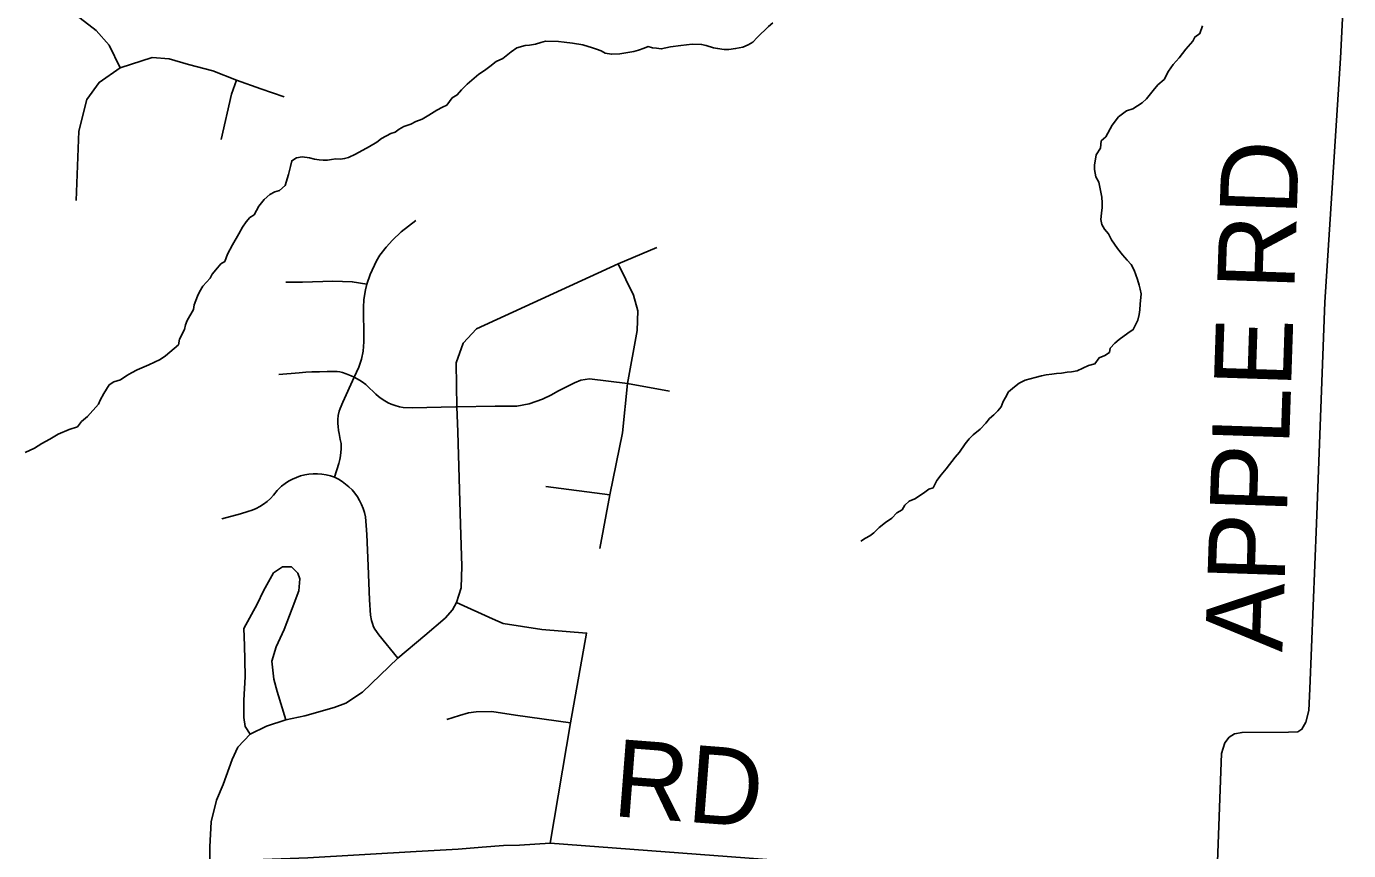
# Model space of a CAD drawing. Extents: x 0 to 34, y 0 to 22.
# Drawn here: x 3.128 to 4.1, y 15.409 to 16.016 of the extents above; entities that cross this region are included whole.
import ezdxf

# ---------------------------------------------------------------- set-up
doc = ezdxf.new("R2010")
doc.units = 0
for name, color, linetype in [('GM_X_Minor_River', 7, 'Continuous'), ('GM_X_Township_Road', 7, 'Continuous'), ('GM_X_Township_Road_Text', 7, 'Continuous')]:
    doc.layers.add(name, color=color, linetype=linetype)

msp = doc.modelspace()

# ---------------------------------------------------------------- linework, layer by layer
at = {"layer": 'GM_X_Minor_River'}
for points in [[(3.67652, 16.01808), (3.67344, 16.01547), (3.66494, 16.00726), (3.66184, 16.00389), (3.65839, 16.00205), (3.65455, 16.00022), (3.64921, 15.99917), (3.64426, 15.9985), (3.64084, 15.99856), (3.63591, 15.9994), (3.63288, 15.99984)], [(3.99241, 16.01596), (3.99042, 16.01029), (3.98695, 16.00769), (3.98538, 16.00467), (3.98034, 15.99868), (3.97529, 15.99231), (3.97103, 15.98744), (3.96752, 15.98256), (3.96438, 15.97653), (3.95975, 15.97243), (3.95626, 15.96831), (3.95122, 15.96232), (3.94812, 15.95933), (3.94121, 15.9549), (3.93662, 15.95345), (3.93084, 15.94899), (3.92618, 15.94299), (3.92148, 15.93433), (3.918, 15.93135), (3.91753, 15.92604), (3.91441, 15.92115), (3.91314, 15.91357), (3.91309, 15.91015), (3.91414, 15.90481), (3.91635, 15.90097), (3.91775, 15.89372), (3.91845, 15.88991), (3.91876, 15.88572), (3.9187, 15.88231), (3.91825, 15.87813), (3.9178, 15.87358), (3.91849, 15.86976), (3.92033, 15.86631), (3.92332, 15.86284), (3.92553, 15.85862), (3.92998, 15.85207), (3.9337, 15.84745), (3.93706, 15.84359), (3.94005, 15.8405), (3.94226, 15.83628), (3.94481, 15.82939), (3.94588, 15.82519), (3.94658, 15.82214), (3.94729, 15.8187)], [(3.63288, 15.99984), (3.62758, 16.00145), (3.62418, 16.00227), (3.61733, 16.00239), (3.60895, 16.0014), (3.60133, 16.00039), (3.59447, 15.99899), (3.59105, 15.99943), (3.58802, 15.99986), (3.58499, 16.00068), (3.58193, 15.99959), (3.57772, 15.99815), (3.57429, 15.99706), (3.56399, 15.99535), (3.5579, 15.99507), (3.55336, 15.99591), (3.55034, 15.99748), (3.54694, 15.99868), (3.54392, 15.99988), (3.53673, 16.0019), (3.52915, 16.00318), (3.52308, 16.00404), (3.5189, 16.0045), (3.5094, 16.00466), (3.50596, 16.00359), (3.50214, 16.00251), (3.49757, 16.00183), (3.49452, 16.0015), (3.48841, 15.99971), (3.48418, 15.99675), (3.47801, 15.99191), (3.47303, 15.98972), (3.46841, 15.986), (3.46456, 15.98303), (3.46033, 15.98044), (3.45532, 15.97597), (3.45184, 15.97299), (3.44759, 15.96888), (3.44449, 15.96513), (3.44065, 15.96292), (3.43676, 15.95767), (3.43369, 15.9562), (3.42948, 15.95399), (3.42371, 15.95029), (3.41872, 15.94734), (3.41413, 15.94552), (3.41029, 15.94369), (3.40532, 15.94188), (3.40187, 15.94004), (3.39879, 15.93781), (3.39573, 15.93672), (3.38883, 15.93304), (3.38536, 15.93044), (3.37998, 15.92712), (3.36962, 15.9216), (3.36464, 15.91902), (3.36159, 15.91832), (3.35854, 15.91799), (3.35512, 15.91805), (3.35207, 15.91772), (3.34902, 15.91702), (3.34598, 15.91707), (3.34294, 15.9175), (3.33953, 15.91794), (3.33574, 15.91877), (3.33044, 15.91962), (3.32624, 15.91894), (3.32278, 15.91672), (3.32195, 15.91255), (3.32033, 15.9065), (3.31792, 15.89856), (3.31367, 15.89483), (3.31023, 15.89375), (3.30678, 15.89191), (3.30253, 15.88819), (3.29865, 15.88331), (3.29512, 15.87691), (3.29205, 15.87507), (3.28933, 15.87169), (3.28661, 15.86794), (3.28387, 15.86305), (3.27916, 15.85477), (3.27563, 15.84799), (3.27364, 15.8427), (3.27057, 15.84086), (3.26823, 15.83786), (3.26436, 15.83336), (3.26279, 15.83035), (3.25737, 15.82436), (3.25501, 15.82022), (3.25344, 15.81721), (3.25224, 15.81381), (3.25105, 15.81079), (3.25062, 15.80738), (3.24592, 15.7991), (3.24473, 15.79608), (3.24391, 15.79267), (3.24037, 15.78551), (3.23954, 15.78135), (3.2299, 15.77315), (3.22605, 15.77056)], [(3.94729, 15.8187), (3.94678, 15.81111), (3.94633, 15.80693), (3.94589, 15.80352), (3.94506, 15.79935), (3.94153, 15.79257), (3.93768, 15.78998), (3.93114, 15.78515), (3.92805, 15.78254), (3.92457, 15.77881), (3.92414, 15.77577), (3.92068, 15.77355), (3.91647, 15.77172), (3.91335, 15.76722), (3.90877, 15.76616), (3.90034, 15.76213), (3.89614, 15.76144), (3.8931, 15.76111), (3.8889, 15.76043), (3.8851, 15.76011), (3.88167, 15.75979), (3.87748, 15.75911), (3.87404, 15.75841), (3.86946, 15.75735), (3.8622, 15.75519), (3.8576, 15.75299), (3.85414, 15.75039), (3.8499, 15.74667), (3.84755, 15.74253), (3.84597, 15.73951), (3.84439, 15.73574), (3.84206, 15.73274), (3.83897, 15.72975), (3.83588, 15.72715), (3.83316, 15.72377), (3.82891, 15.71929), (3.8239, 15.71519), (3.8208, 15.71221), (3.81808, 15.70845), (3.8138, 15.70244), (3.81069, 15.6987), (3.80409, 15.69007), (3.80021, 15.68558), (3.7971, 15.68145), (3.79435, 15.67618), (3.79129, 15.67509), (3.78821, 15.67286), (3.78513, 15.67064), (3.78091, 15.66805), (3.77669, 15.66622), (3.7736, 15.66324), (3.77164, 15.65985), (3.7678, 15.65764), (3.76394, 15.6539), (3.75932, 15.65056), (3.7547, 15.64684), (3.75083, 15.64311), (3.74776, 15.64088), (3.74468, 15.63904), (3.74123, 15.63682)], [(3.22605, 15.77056), (3.21762, 15.76652), (3.20919, 15.76287), (3.20498, 15.76067), (3.20152, 15.75883), (3.1969, 15.75549), (3.19194, 15.75405), (3.18848, 15.75183), (3.18457, 15.74544), (3.18183, 15.74055), (3.18063, 15.73753), (3.1725, 15.72855), (3.16826, 15.72482), (3.16515, 15.72107), (3.15903, 15.7189), (3.15099, 15.71562), (3.14485, 15.71193), (3.13909, 15.70861), (3.13371, 15.70528), (3.12681, 15.70198)]]:
    msp.add_lwpolyline(points, dxfattribs=at)
at = {"layer": 'GM_X_Township_Road'}
for p, q in [((4.07763, 15.68252), (4.08239, 15.81272)), ((3.50975, 15.67713), (3.55663, 15.67093))]:
    msp.add_line(p, q, dxfattribs=at)
for points in [[(4.08239, 15.81272), (4.09405, 15.99209), (4.0999, 16.10906)], [(3.13895, 16.04607), (3.14583, 16.03823), (3.17898, 16.01249), (3.18851, 16.00169), (3.19656, 15.98496)], [(3.16428, 15.88758), (3.16627, 15.93837), (3.17199, 15.96166), (3.1811, 15.97437), (3.19656, 15.98496), (3.22004, 15.99262), (3.23253, 15.99175), (3.24689, 15.98745), (3.26464, 15.98274), (3.28218, 15.97601), (3.30011, 15.96952), (3.31729, 15.96367)], [(3.27089, 15.93223), (3.27852, 15.96569), (3.28218, 15.97601)], [(3.35423, 15.68387), (3.35739, 15.69407), (3.35811, 15.69697), (3.35856, 15.69961), (3.35896, 15.70245), (3.35917, 15.70458), (3.35917, 15.70631), (3.35902, 15.70875), (3.35851, 15.71164), (3.35765, 15.71617), (3.35719, 15.71835), (3.35683, 15.72129), (3.35673, 15.72347), (3.35673, 15.72642), (3.35704, 15.72927), (3.35775, 15.73242), (3.35846, 15.73455), (3.36024, 15.73902), (3.36873, 15.7576), (3.37216, 15.76487), (3.37416, 15.7708), (3.37531, 15.77654), (3.37588, 15.78342), (3.37588, 15.79289), (3.3756, 15.80207), (3.3756, 15.80867), (3.37588, 15.81469), (3.37693, 15.82167), (3.37788, 15.8259), (3.38047, 15.83297), (3.38506, 15.843), (3.38765, 15.84731), (3.39223, 15.85304), (3.3968, 15.85836), (3.40321, 15.86435), (3.41404, 15.87283)], [(3.32781, 15.50749), (3.3325, 15.50845), (3.35398, 15.51461), (3.36244, 15.51775), (3.37484, 15.52569), (3.4007, 15.55083), (3.4207, 15.56759), (3.43562, 15.58025), (3.44097, 15.58646), (3.44385, 15.59169), (3.44747, 15.60246), (3.44776, 15.61848), (3.44689, 15.64921), (3.44484, 15.71722), (3.44423, 15.7356), (3.44382, 15.75145), (3.44368, 15.76805), (3.44878, 15.78262), (3.45854, 15.79296), (3.56282, 15.8408), (3.59116, 15.85286)], [(3.54926, 15.63141), (3.55663, 15.67093), (3.56592, 15.71665), (3.56975, 15.75287), (3.57677, 15.79181), (3.57738, 15.80636), (3.57406, 15.81777), (3.56282, 15.8408)], [(3.31837, 15.82728), (3.33079, 15.82745), (3.3531, 15.82812), (3.36728, 15.8277), (3.37788, 15.8259)], [(3.31319, 15.75942), (3.32823, 15.76077), (3.33305, 15.76115), (3.33748, 15.76135), (3.3432, 15.76154), (3.34873, 15.76173), (3.35355, 15.76179), (3.35612, 15.76167), (3.35811, 15.76141), (3.36004, 15.76096), (3.36287, 15.76006), (3.36653, 15.75858), (3.36873, 15.7576), (3.37257, 15.75537), (3.37463, 15.75408), (3.37733, 15.75209), (3.3788, 15.75065), (3.38028, 15.7492), (3.38241, 15.74727), (3.38472, 15.74502), (3.38665, 15.74341), (3.38864, 15.74187), (3.39114, 15.7402), (3.39366, 15.73866), (3.3959, 15.73763), (3.39879, 15.7366), (3.40194, 15.73577), (3.40471, 15.73526), (3.41134, 15.73496), (3.44337, 15.73557), (3.44423, 15.7356), (3.47228, 15.7363), (3.4884, 15.73621), (3.49739, 15.73787), (3.50711, 15.74121), (3.51388, 15.74455), (3.51841, 15.74723), (3.5249, 15.75047), (3.53074, 15.75344), (3.53527, 15.75529), (3.54176, 15.75631), (3.56975, 15.75287), (3.60054, 15.7473)], [(3.27127, 15.65323), (3.28501, 15.65687), (3.29053, 15.65864), (3.29359, 15.65966), (3.29656, 15.66093), (3.29941, 15.66245), (3.30213, 15.6642), (3.30469, 15.66617), (3.30707, 15.66835), (3.30927, 15.67071), (3.31215, 15.67408), (3.31301, 15.67509), (3.31535, 15.67725), (3.31786, 15.67921), (3.32052, 15.68095), (3.32332, 15.68248), (3.32622, 15.68377), (3.32923, 15.68481), (3.33231, 15.6856), (3.33545, 15.68614), (3.33863, 15.68641), (3.34181, 15.68642), (3.34498, 15.68617), (3.34812, 15.68566), (3.35121, 15.68489), (3.35423, 15.68387), (3.35709, 15.68243), (3.35983, 15.68077), (3.36242, 15.67889), (3.36486, 15.6768), (3.36712, 15.67453), (3.3692, 15.67209), (3.37107, 15.66948), (3.37273, 15.66674), (3.37416, 15.66388), (3.37536, 15.6609), (3.37632, 15.65785), (3.37703, 15.65472), (3.37761, 15.64841), (3.37793, 15.64183), (3.37891, 15.61871), (3.37988, 15.59371), (3.38078, 15.58249), (3.38145, 15.57853), (3.38205, 15.5762), (3.38287, 15.57396), (3.38385, 15.57224), (3.38504, 15.57037), (3.38676, 15.56797), (3.4007, 15.55083)], [(4.00308, 15.38767), (4.00648, 15.48067), (4.00895, 15.48858), (4.01209, 15.49267), (4.01595, 15.49523), (4.02166, 15.49622), (4.05576, 15.49648), (4.06258, 15.49668), (4.06565, 15.4985), (4.06844, 15.50373), (4.07057, 15.51241), (4.07136, 15.52832), (4.07644, 15.64997), (4.07763, 15.68252)], [(3.29212, 15.495), (3.2886, 15.50056), (3.28767, 15.50723), (3.28767, 15.52001), (3.2886, 15.53705), (3.28841, 15.54947), (3.28804, 15.56021), (3.28748, 15.57257), (3.29731, 15.59059), (3.30194, 15.60023), (3.30935, 15.61357), (3.31611, 15.61806), (3.32266, 15.6179), (3.32719, 15.61337), (3.32862, 15.60912), (3.32806, 15.60023), (3.32306, 15.58726), (3.31731, 15.57188), (3.31139, 15.5591), (3.30805, 15.54854), (3.30972, 15.53539), (3.31213, 15.52631), (3.31843, 15.50556)], [(3.51277, 15.4146), (3.52784, 15.50325), (3.53963, 15.56929), (3.5066, 15.57195), (3.47817, 15.57628), (3.47052, 15.57983), (3.44385, 15.59169)], [(3.26266, 15.40126), (3.26248, 15.412), (3.26359, 15.43053), (3.26748, 15.44628), (3.2723, 15.45776), (3.27897, 15.47629), (3.28305, 15.48538), (3.29212, 15.495), (3.30416, 15.50074), (3.31843, 15.50556), (3.32781, 15.50749)], [(3.43681, 15.50575), (3.44607, 15.50852), (3.45274, 15.51056), (3.45848, 15.5113), (3.46997, 15.51149), (3.4872, 15.50889), (3.52784, 15.50325)], [(2.87769, 15.41938), (3.05259, 15.40036), (3.07886, 15.39727), (3.09409, 15.39564), (3.122, 15.39347), (3.16133, 15.39437), (3.2012, 15.39709), (3.26266, 15.40126), (3.33454, 15.40403), (3.4142, 15.40848), (3.44514, 15.41034), (3.46293, 15.41182), (3.47849, 15.41293), (3.49035, 15.4133), (3.51277, 15.4146), (3.71766, 15.39922), (3.75193, 15.39699), (3.76601, 15.39699), (3.78398, 15.39755), (3.79362, 15.39811), (3.80399, 15.39811), (3.81399, 15.39867), (4.00308, 15.38767)]]:
    msp.add_lwpolyline(points, dxfattribs=at)

# ---------------------------------------------------------------- texts
at = {"layer": 'GM_X_Township_Road_Text'}
for s, rotation, p in [('APPLE RD', 88.10497, (4.05118, 15.55505)), ('RD', 355.56412, (3.55787, 15.43475))]:
    msp.add_text(s, height=0.056818, rotation=rotation, dxfattribs=at).set_placement(p)

doc.saveas('drawing.dxf')
